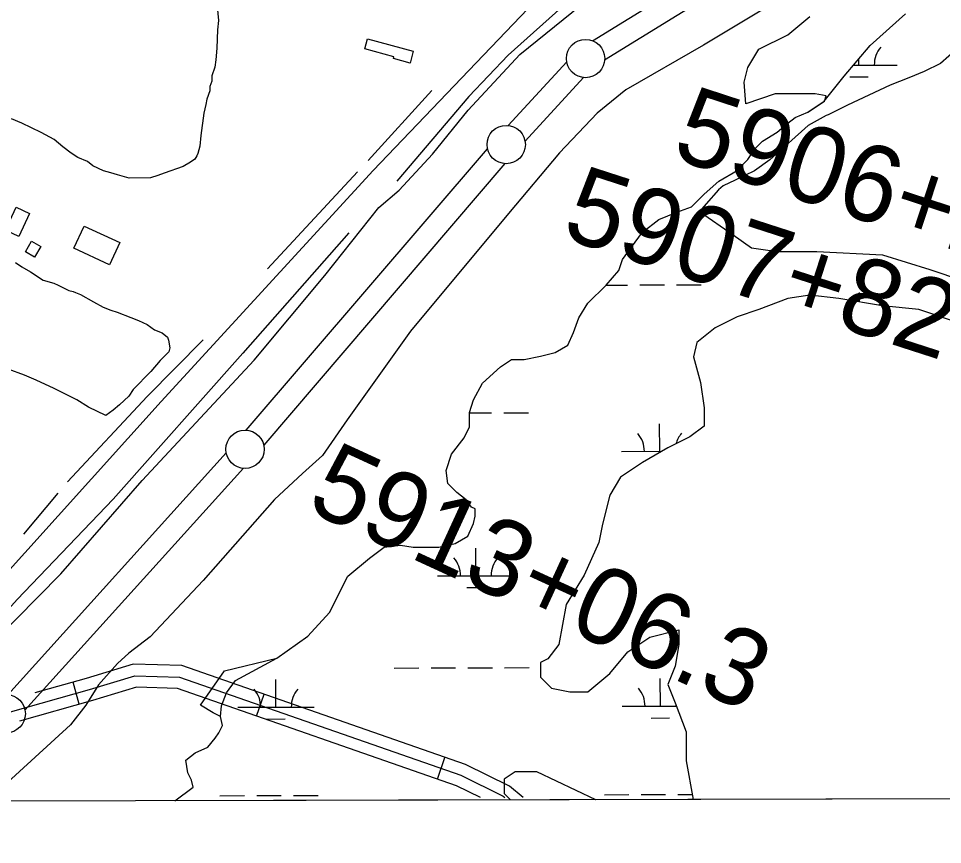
# Model space of a CAD drawing. Extents: x 3355724 to 3393621, y 594744 to 620174.
# Drawn here: x 3381436 to 3382643, y 600128 to 601207 of the extents above; entities that cross this region are included whole.
import ezdxf

# ---------------------------------------------------------------- set-up
doc = ezdxf.new("R2010")
doc.units = 0
for name, color, linetype in [('V-BLDG-OTLN', 7, 'Continuous'), ('V-GRID-FRAM', 7, 'Continuous'), ('V-LEVE-TOET', 7, 'Continuous'), ('V-ROAD-CNTR', 7, 'Continuous'), ('V-SITE-VEGE', 7, 'Continuous'), ('V-SURV-IDEN', 7, 'Continuous'), ('V-SURV-LINE', 7, 'Continuous'), ('V-TOPO-SHOR', 7, 'Continuous'), ('V-WETL-SWMP', 7, 'Continuous')]:
    doc.layers.add(name, color=color, linetype=linetype)

msp = doc.modelspace()

# ---------------------------------------------------------------- linework, layer by layer
at = {"layer": 'V-BLDG-OTLN'}
for points in [[(3381892.2, 601180.2), (3381951.7, 601164.2), (3381947.5, 601148.7), (3381925.8, 601154.5), (3381926.5, 601157), (3381888.7, 601167.1)], [(3381433.3, 600960.5), (3381450.9, 600952.4), (3381436.9, 600922.3), (3381419.4, 600930.5)], [(3381522.2, 600935.9), (3381568.6, 600914.2), (3381555, 600885.1), (3381508.6, 600906.8)], [(3381453.5, 600916.2), (3381465.4, 600909.3), (3381457.4, 600895.4), (3381445.5, 600902.2)]]:
    msp.add_lwpolyline(points, close=True, dxfattribs=at)
at = {"layer": 'V-GRID-FRAM'}
msp.add_lwpolyline([(3359807.6, 618312.1), (3391397.2, 618394.8), (3391452.7, 600211.2), (3359847.2, 600128.5), (3359807.6, 618312.1)], dxfattribs=at)
at = {"layer": 'V-LEVE-TOET'}
for points in [[(3381230.7, 600184.5), (3381250.2, 600207.8), (3381264.3, 600227.5), (3381272.4, 600244.4), (3381294.5, 600270.6), (3381373.7, 600362.6), (3381491.8, 600481.8), (3381597.9, 600603.6), (3381744.2, 600760.9), (3381836.5, 600871.3), (3381906.9, 600960.1), (3381933.2, 600982.9), (3381976.7, 601029.7), (3382023.5, 601087), (3382091.1, 601160), (3382170, 601224), (3382258.2, 601278.4), (3382381, 601355.6), (3382524.7, 601439.4), (3382671.2, 601529.6)], [(3382761.1, 601433.9), (3382600.7, 601334.5), (3382474.4, 601258.6), (3382330.7, 601172), (3382229.3, 601113.9), (3382191.9, 601083.3), (3382142.9, 601031.6), (3382076.1, 600952.3), (3381948, 600798.7), (3381865.6, 600682.9), (3381833.3, 600636.2), (3381807, 600612.8), (3381770.4, 600578.7), (3381677.3, 600473.2), (3381608.3, 600399.5), (3381580.6, 600378.1), (3381565.4, 600364.6), (3381540.6, 600337), (3381524.1, 600310.2), (3381504.2, 600284.7), (3381411.6, 600200.2), (3381398.5, 600184.9)]]:
    msp.add_lwpolyline(points, dxfattribs=at)
at = {"layer": 'V-ROAD-CNTR'}
for p, q in [((3381515.7, 600311.6), (3381507.5, 600340.4)), ((3381747.1, 600296.2), (3381757, 600324.6)), ((3381983.2, 600213.9), (3381993.1, 600242.2))]:
    msp.add_line(p, q, dxfattribs=at)
for points in [[(3382101.4, 601219.4), (3381899.2, 601008.2), (3381622.5, 600706.8), (3381309.8, 600359.8), (3381148.4, 600187.3)], [(3382095.4, 600189.8), (3382077.2, 600204.5), (3382019.8, 600232.9), (3381649.5, 600362.1), (3381586.2, 600363.8), (3381524.7, 600345.3), (3381457.8, 600326.3)], [(3381197.4, 600239.7), (3381228.2, 600235.5), (3381255.7, 600235.8), (3381373.2, 600284.1), (3381426, 600301.6), (3381528.9, 600330.9), (3381588.2, 600348.7), (3381646.7, 600347.1), (3382014, 600219), (3382069.1, 600191.7), (3382071.5, 600189.8)], [(3382039.4, 600189.7), (3382008.2, 600205.2), (3381644, 600332.2), (3381590.2, 600333.7), (3381533.1, 600316.5), (3381437.8, 600289.4)]]:
    msp.add_lwpolyline(points, dxfattribs=at)
at = {"layer": 'V-SITE-VEGE'}
for p, q in [((3382441, 601185.6), (3382469.5, 601209.3)), ((3382403, 601166.6), (3382441, 601185.6)), ((3382388.7, 601142.8), (3382403, 601166.6)), ((3382384, 601123.8), (3382388.7, 601142.8)), ((3382385.9, 601095.5), (3382384, 601123.8)), ((3382424.4, 601108.3), (3382385.9, 601095.5)), ((3382476.6, 601108.3), (3382424.4, 601108.3)), ((3382490.8, 601106), (3382476.6, 601108.3)), ((3382488.5, 601098.8), (3382490.8, 601106)), ((3382467.1, 601084.6), (3382488.5, 601098.8)), ((3382450.5, 601077.5), (3382467.1, 601084.6)), ((3382426.7, 601058.5), (3382441, 601070.3)), ((3382441, 601070.3), (3382450.5, 601077.5)), ((3382407.7, 601046.6), (3382426.7, 601058.5)), ((3382398.2, 601037.1), (3382407.7, 601046.6)), ((3382388.7, 601022.8), (3382398.2, 601037.1)), ((3382374.5, 601008.6), (3382388.7, 601022.8)), ((3382350.7, 600994.3), (3382374.5, 601008.6)), ((3382331.7, 600977.7), (3382350.7, 600994.3)), ((3382315.1, 600961.1), (3382331.7, 600977.7)), ((3382296.1, 600953.9), (3382315.1, 600961.1)), ((3382272.4, 600944.4), (3382296.1, 600953.9)), ((3382251, 600927.8), (3382272.4, 600944.4)), ((3382232, 600901.7), (3382251, 600927.8)), ((3382224.9, 600892.2), (3382232, 600901.7)), ((3382220.1, 600877.9), (3382224.9, 600892.2)), ((3382203.5, 600858.9), (3382220.1, 600877.9)), ((3382179.8, 600835.1), (3382203.5, 600858.9)), ((3382167.9, 600816.1), (3382179.8, 600835.1)), ((3382160.8, 600797.1), (3382167.9, 600816.1)), ((3382153.7, 600780.5), (3382160.8, 600797.1)), ((3382137, 600771), (3382153.7, 600780.5)), ((3382118, 600766.2), (3382137, 600771)), ((3382065.8, 600752), (3382080.1, 600761.5)), ((3382080.1, 600761.5), (3382096.7, 600761.5)), ((3382096.7, 600761.5), (3382118, 600766.2)), ((3382042.1, 600730.6), (3382065.8, 600752)), ((3382030.2, 600709.2), (3382042.1, 600730.6)), ((3382025.4, 600692.6), (3382030.2, 600709.2)), ((3382025.4, 600673.6), (3382025.4, 600692.6)), ((3382018.3, 600659.3), (3382025.4, 600673.6)), ((3382001.7, 600637.9), (3382018.3, 600659.3)), ((3381994.6, 600616.6), (3382001.7, 600637.9)), ((3381996.9, 600599.9), (3381994.6, 600616.6)), ((3382008.8, 600588.1), (3381996.9, 600599.9)), ((3382020.7, 600578.5), (3382008.8, 600588.1)), ((3382027.8, 600569), (3382020.7, 600578.5)), ((3382032.6, 600566.7), (3382027.8, 600569)), ((3382032.6, 600557.2), (3382032.6, 600566.7)), ((3382030.2, 600547.7), (3382032.6, 600557.2)), ((3382023.1, 600531), (3382030.2, 600547.7)), ((3382006.4, 600521.5), (3382023.1, 600531)), ((3381894.8, 600502.5), (3381913.8, 600516.8)), ((3381913.8, 600516.8), (3381935.2, 600519.2)), ((3381935.2, 600519.2), (3381951.8, 600516.8)), ((3381951.8, 600516.8), (3381985.1, 600516.8)), ((3381985.1, 600516.8), (3382006.4, 600521.5)), ((3381866.4, 600478.8), (3381894.8, 600502.5)), ((3381842.6, 600431.2), (3381866.4, 600478.8)), ((3381814.1, 600400.4), (3381842.6, 600431.2)), ((3381773.7, 600371.9), (3381814.1, 600400.4)), ((3381705.4, 600355.4), (3381773.7, 600371.9)), ((3381673.9, 600310.6), (3381705.4, 600355.4)), ((3381690.6, 600300.6), (3381673.9, 600310.6)), ((3381700.1, 600295.8), (3381690.6, 600300.6)), ((3381702.5, 600283.9), (3381700.1, 600295.8)), ((3381693, 600267.3), (3381697.8, 600274.4)), ((3381697.8, 600274.4), (3381702.5, 600283.9)), ((3381683.5, 600255.4), (3381693, 600267.3)), ((3381666.9, 600248.3), (3381683.5, 600255.4)), ((3381655, 600238.8), (3381666.9, 600248.3)), ((3381657.4, 600222.2), (3381655, 600238.8)), ((3381662.1, 600212.7), (3381657.4, 600222.2)), ((3381664.5, 600203.2), (3381662.1, 600212.7)), ((3381640.3, 600185.5), (3381664.5, 600203.2)), ((3385211.8, 600194.9), (3381640.3, 600185.5))]:
    msp.add_line(p, q, dxfattribs=at)
for points in [[(3381695.9, 601222.4), (3381697.5, 601204.4), (3381696.3, 601191.9), (3381695.2, 601168.2), (3381694, 601152.9), (3381692.7, 601143.2), (3381688.7, 601132), (3381688.8, 601125.1), (3381686.1, 601118.1), (3381686.2, 601112.5), (3381682.2, 601101.4), (3381680.9, 601094.4), (3381678.3, 601083.3), (3381674.5, 601054), (3381673.3, 601040.1), (3381670.6, 601030.4), (3381669.3, 601027.6), (3381666.6, 601023.4), (3381661.1, 601019.1), (3381651.4, 601013.5), (3381626.5, 601004.8), (3381618.2, 601001.9), (3381608.6, 600999), (3381580.8, 600998.6), (3381565.5, 601002.6), (3381557.1, 601005.2), (3381547.3, 601007.9), (3381533.3, 601014.6), (3381526.3, 601020.1), (3381513.8, 601025.5), (3381505.3, 601030.9), (3381494.1, 601039.1), (3381482.9, 601048.7), (3381466.1, 601058.2), (3381440.9, 601070.4), (3381427, 601075.7)], [(3381432.3, 600888.3), (3381440.7, 600882.8), (3381451.9, 600876), (3381468.7, 600865.2), (3381482.6, 600861.2), (3381488.2, 600858.5), (3381502.2, 600851.7), (3381507.8, 600850.4), (3381510.6, 600849), (3381517.5, 600846.4), (3381534.3, 600836.9), (3381546.9, 600830.1), (3381556.7, 600826.1), (3381565.1, 600823.4), (3381583.2, 600816.7), (3381593, 600812.6), (3381604.2, 600807.2), (3381614, 600800.4), (3381623.8, 600796.4), (3381630.8, 600790.9), (3381632.2, 600786.8), (3381633.8, 600777.1), (3381632.5, 600771.5), (3381621.5, 600760.2), (3381609.2, 600746.2), (3381585.9, 600722.3), (3381580.4, 600713.9), (3381568.1, 600702.6), (3381559.9, 600695.5), (3381550.2, 600688.4), (3381527.9, 600699.3), (3381512.4, 600708.8), (3381494.3, 600718.3), (3381483.1, 600723.7), (3381459.3, 600734.5), (3381444, 600741.2), (3381423, 600749.2)]]:
    msp.add_lwpolyline(points, dxfattribs=at)
at = {"layer": 'V-SURV-LINE'}
for points in [[(3382185.9, 601177.9), (3382766.3, 601535.1)], [(3382782.1, 601509.6), (3382201.6, 601152.3)], [(3382075.7, 601067.1), (3382152.1, 601150.1)], [(3382174.2, 601129.8), (3382097.7, 601046.8)], [(3381733.7, 600669.5), (3382048.7, 601036.9)], [(3382071.5, 601017.4), (3381756.5, 600649.9)], [(3381422.5, 600324.1), (3381707.6, 600639.7)], [(3381729.9, 600619.6), (3381444.8, 600304)]]:
    msp.add_lwpolyline(points, dxfattribs=at)
for centre in [(3382176.7, 601154.6), (3382073.1, 601042.3), (3381732.1, 600644.5), (3381420.3, 600299.2)]:
    msp.add_circle(centre, 25, dxfattribs=at)
at = {"layer": 'V-TOPO-SHOR'}
for p, q in [((3381975.8, 601112.9), (3381893, 601021.5)), ((3381879.1, 601006.5), (3381761.6, 600880.1)), ((3381487.8, 600587), (3381443, 600533.8))]:
    msp.add_line(p, q, dxfattribs=at)
for points in [[(3383162.5, 601892.2), (3382955, 601742.7), (3382818.2, 601651.4), (3382675.8, 601562.4), (3382583.3, 601501.5), (3382481.3, 601437.4), (3382341.2, 601354.7), (3382225.4, 601278.6), (3382153.9, 601229), (3382075.6, 601158.9), (3382024.5, 601104.9), (3381930.3, 600994.6)], [(3381867.6, 600927.1), (3381729.3, 600769.9), (3381560.1, 600579.3), (3381434.7, 600448.2), (3381295.6, 600293.3), (3381242.2, 600236.1)], [(3381677.3, 600787.2), (3381604.5, 600713.3), (3381500.1, 600602)]]:
    msp.add_lwpolyline(points, dxfattribs=at)
at = {"layer": 'V-WETL-SWMP'}
for p, q in [((3382548.4, 601171.6), (3382594.3, 601213.1)), ((3382514.4, 601131.6), (3382548.4, 601171.6)), ((3382661.9, 601167.4), (3382640.1, 601148.2)), ((3382533.6, 601146), (3382533.6, 601154.2)), ((3382526.6, 601145.9), (3382583.6, 601146.1)), ((3382640.1, 601148.2), (3382619, 601137.7)), ((3382488.4, 601098.8), (3382514.4, 601131.6)), ((3382521.7, 601130.5), (3382545.7, 601130.6)), ((3382598.7, 601129.5), (3382574.4, 601119.8)), ((3382619, 601137.7), (3382598.7, 601129.5)), ((3382574.4, 601119.8), (3382518.9, 601093.8)), ((3382467.1, 601084.6), (3382488.4, 601098.8)), ((3382518.9, 601093.8), (3382493.3, 601081.3)), ((3382450.4, 601077.5), (3382467.1, 601084.6)), ((3382493.3, 601081.3), (3382490.7, 601080.1)), ((3382426.7, 601058.5), (3382440.9, 601070.3)), ((3382440.9, 601070.3), (3382450.4, 601077.5)), ((3382490.7, 601080.1), (3382467.3, 601067.2)), ((3382407.7, 601046.6), (3382426.7, 601058.5)), ((3382467.3, 601067.2), (3382441.6, 601044)), ((3382398.2, 601037.1), (3382407.7, 601046.6)), ((3382388.7, 601022.8), (3382398.2, 601037.1)), ((3382441.6, 601044), (3382417.5, 601022.4)), ((3382374.5, 601008.6), (3382388.7, 601022.8)), ((3382417.5, 601022.4), (3382397.3, 601008)), ((3382350.7, 600994.3), (3382374.5, 601008.6)), ((3382397.3, 601008), (3382372.2, 600995.9)), ((3382331.7, 600977.7), (3382350.7, 600994.3)), ((3382356.6, 600988.6), (3382350.4, 600983)), ((3382372.2, 600995.9), (3382356.6, 600988.6)), ((3382315.1, 600961), (3382331.7, 600977.7)), ((3382350.4, 600983), (3382334.1, 600964.7)), ((3382296.1, 600953.9), (3382315.1, 600961)), ((3382334.1, 600964.7), (3382325.5, 600955.1)), ((3382272.4, 600944.4), (3382296.1, 600953.9)), ((3382325.5, 600955.1), (3382369.5, 600924.3)), ((3382251, 600927.8), (3382272.4, 600944.4)), ((3382232, 600901.6), (3382251, 600927.8)), ((3382369.5, 600924.3), (3382393.5, 600907.6)), ((3382224.9, 600892.1), (3382232, 600901.6)), ((3382393.5, 600907.6), (3382426.7, 600902.8)), ((3382426.7, 600902.8), (3382478.9, 600902.8)), ((3382478.9, 600902.8), (3382564.4, 600898.1)), ((3382220.1, 600877.9), (3382224.9, 600892.1)), ((3382564.4, 600898.1), (3382626.1, 600879.1)), ((3382203.5, 600858.9), (3382220.1, 600877.9)), ((3382626.1, 600879.1), (3382668.9, 600864.8)), ((3382179.8, 600835.1), (3382203.5, 600858.9)), ((3382203.5, 600858.8), (3382231.6, 600858.9)), ((3382247.6, 600859), (3382279.6, 600859)), ((3382295.6, 600859.1), (3382327.6, 600859.2)), ((3382440.9, 600841.1), (3382402.9, 600826.8)), ((3382469.4, 600845.8), (3382440.9, 600841.1)), ((3382507.4, 600841.1), (3382469.4, 600845.8)), ((3382564.4, 600831.6), (3382507.4, 600841.1)), ((3382534.5, 600836.6), (3382534.4, 600849.3)), ((3382167.9, 600816.1), (3382179.8, 600835.1)), ((3382611.9, 600826.8), (3382564.4, 600831.6)), ((3382160.8, 600797.1), (3382167.9, 600816.1)), ((3382374.5, 600817.3), (3382346, 600803.1)), ((3382402.9, 600826.8), (3382374.5, 600817.3)), ((3382654.6, 600812.6), (3382611.9, 600826.8)), ((3382153.6, 600780.5), (3382160.8, 600797.1)), ((3382346, 600803.1), (3382322.2, 600784)), ((3382137, 600771), (3382153.6, 600780.5)), ((3382322.2, 600784), (3382317.5, 600765)), ((3382118, 600766.2), (3382137, 600771)), ((3382065.8, 600752), (3382080, 600761.5)), ((3382080, 600761.5), (3382096.6, 600761.5)), ((3382096.6, 600761.5), (3382118, 600766.2)), ((3382317.5, 600765), (3382327, 600731.8)), ((3382042, 600730.6), (3382065.8, 600752)), ((3382327, 600731.8), (3382331.7, 600698.5)), ((3382030.2, 600709.2), (3382042, 600730.6)), ((3382025.4, 600692.6), (3382030.2, 600709.2)), ((3382331.7, 600698.5), (3382331.7, 600684.3)), ((3382025.4, 600673.6), (3382025.4, 600692.6)), ((3382025.4, 600691.9), (3382054.1, 600692)), ((3382070.1, 600692), (3382102.1, 600692.1)), ((3382331.7, 600684.3), (3382331.7, 600674.8)), ((3382018.3, 600659.3), (3382025.4, 600673.6)), ((3382273.5, 600641.8), (3382273.4, 600677.8)), ((3382331.7, 600674.8), (3382312.7, 600660.5)), ((3382001.7, 600637.9), (3382018.3, 600659.3)), ((3382312.7, 600660.5), (3382284.2, 600646.3)), ((3381994.6, 600616.6), (3382001.7, 600637.9)), ((3382223.5, 600641.7), (3382276.4, 600641.8)), ((3382284.2, 600646.3), (3382251, 600627.2)), ((3382251, 600627.2), (3382222.5, 600608.2)), ((3381996.9, 600599.9), (3381994.6, 600616.6)), ((3382008.8, 600588), (3381996.9, 600599.9)), ((3382222.5, 600608.2), (3382208.2, 600584.5)), ((3382020.7, 600578.5), (3382008.8, 600588)), ((3382027.8, 600569), (3382020.7, 600578.5)), ((3382208.2, 600584.5), (3382198.7, 600546.5)), ((3382032.5, 600566.7), (3382027.8, 600569)), ((3382032.5, 600557.2), (3382032.5, 600566.7)), ((3382030.2, 600547.7), (3382032.5, 600557.2)), ((3382023, 600531), (3382030.2, 600547.7)), ((3382198.7, 600546.5), (3382194, 600522.7)), ((3382006.4, 600521.5), (3382023, 600531)), ((3381894.8, 600502.5), (3381913.8, 600516.8)), ((3381913.8, 600516.8), (3381935.2, 600519.1)), ((3381935.2, 600519.1), (3381951.8, 600516.8)), ((3381951.8, 600516.8), (3381985.1, 600516.8)), ((3381985.1, 600516.8), (3382006.4, 600521.5)), ((3382033.5, 600479.3), (3382033.4, 600515.3)), ((3382194, 600522.7), (3382175, 600479.9)), ((3381866.3, 600478.8), (3381894.8, 600502.5)), ((3381842.6, 600431.2), (3381866.3, 600478.8)), ((3381983.5, 600479.2), (3382083.5, 600479.4)), ((3382175, 600479.9), (3382151.3, 600441.9)), ((3382021.5, 600463.8), (3382045.5, 600463.9)), ((3382151.3, 600441.9), (3382141.8, 600389.7)), ((3381814.1, 600400.4), (3381842.6, 600431.2)), ((3382260.5, 600399.2), (3382298.5, 600408.7)), ((3382298.5, 600408.7), (3382298.5, 600389.7)), ((3381773.7, 600371.9), (3381814.1, 600400.4)), ((3382232, 600380.2), (3382260.5, 600399.2)), ((3382141.8, 600389.7), (3382127.5, 600370.7)), ((3382298.5, 600389.7), (3382293.7, 600361.2)), ((3381719.6, 600342.8), (3381773.7, 600371.9)), ((3382127.5, 600370.7), (3382118, 600365.9)), ((3382208.2, 600351.7), (3382232, 600380.2)), ((3381927, 600358.9), (3381959, 600359)), ((3381975, 600359.1), (3382007, 600359.2)), ((3382023, 600359.2), (3382055, 600359.3)), ((3382071, 600359.3), (3382103, 600359.4)), ((3382118, 600365.9), (3382118, 600346.9)), ((3382293.7, 600361.2), (3382284.2, 600337.4)), ((3382118, 600346.9), (3382132.3, 600332.6)), ((3382179.8, 600327.9), (3382208.2, 600351.7)), ((3382274.4, 600309.1), (3382274.3, 600345.1)), ((3381707.8, 600326.4), (3381719.6, 600342.8)), ((3381772.5, 600307.8), (3381772.4, 600343.8)), ((3382284.2, 600337.4), (3382293.7, 600313.6)), ((3381701.2, 600309.4), (3381707.8, 600326.4)), ((3382132.3, 600332.6), (3382156, 600327.9)), ((3382156, 600327.9), (3382179.8, 600327.9)), ((3381700.1, 600295.8), (3381701.2, 600309.4)), ((3382224.4, 600309), (3382295.4, 600309.2)), ((3382293.7, 600313.6), (3382308, 600275.6)), ((3381722.5, 600307.7), (3381822.5, 600307.9)), ((3381702.5, 600283.9), (3381700.1, 600295.8)), ((3381760.5, 600292.3), (3381784.5, 600292.4)), ((3382262.4, 600293.6), (3382286.4, 600293.7)), ((3381693, 600267.3), (3381697.8, 600274.4)), ((3381697.8, 600274.4), (3381702.5, 600283.9)), ((3382308, 600275.6), (3382308, 600261.4)), ((3381683.5, 600255.4), (3381693, 600267.3)), ((3382308, 600261.4), (3382308, 600237.6)), ((3381666.9, 600248.3), (3381683.5, 600255.4)), ((3381655, 600238.8), (3381666.9, 600248.3)), ((3381657.4, 600222.2), (3381655, 600238.8)), ((3382308, 600237.6), (3382317.1, 600187.3)), ((3381662.1, 600212.7), (3381657.4, 600222.2)), ((3381664.5, 600203.2), (3381662.1, 600212.7)), ((3382084.8, 600223.4), (3382070.5, 600213.9)), ((3382070.5, 600213.9), (3382070.5, 600194.9)), ((3382113.3, 600223.4), (3382084.8, 600223.4)), ((3382190.1, 600187), (3382113.3, 600223.4)), ((3381640.3, 600185.5), (3381664.5, 600203.2)), ((3381699.4, 600192.2), (3381731.4, 600192.3)), ((3381747.4, 600192.3), (3381779.4, 600192.4)), ((3381795.4, 600192.4), (3381827.4, 600192.5)), ((3382070.5, 600194.9), (3382078.7, 600186.7)), ((3382201.3, 600193.5), (3382233.3, 600193.6)), ((3382249.3, 600193.6), (3382281.3, 600193.7)), ((3382297.3, 600193.7), (3382315.9, 600193.8)), ((3382078.7, 600186.7), (3381640.3, 600185.5)), ((3382317.1, 600187.3), (3382190.1, 600187))]:
    msp.add_line(p, q, dxfattribs=at)
for centre, start, end in [((3382588.9, 601146.6), 139.3782, 180.9218), ((3382589.8, 600813.9), 139.3782, 148.4488), ((3382218.3, 600642.1), 359.3782, 40.9218), ((3382328.8, 600642.4), 139.3782, 165.0469), ((3381978.2, 600479.6), 359.3782, 40.9218), ((3382088.7, 600479.9), 139.3782, 180.9218), ((3381717.3, 600308.1), 359.3782, 40.9218), ((3381827.7, 600308.4), 139.3782, 180.9218), ((3382219.2, 600309.4), 359.3782, 40.9218), ((3382329.6, 600309.7), 176.7852, 180.9218)]:
    msp.add_arc(centre, 35.2, start, end, dxfattribs=at)

# ---------------------------------------------------------------- texts
at = {"layer": 'V-SURV-IDEN'}
for s, rotation, p in [('5906+29.5', 341.8805, (3382286.9, 601025.5)), ('5907+82.3', 342.1054, (3382143, 600921.5)), ('5913+06.3', 335.2938, (3381809.7, 600566.2))]:
    msp.add_text(s, height=100, rotation=rotation, dxfattribs=at).set_placement(p)

doc.saveas('drawing.dxf')
